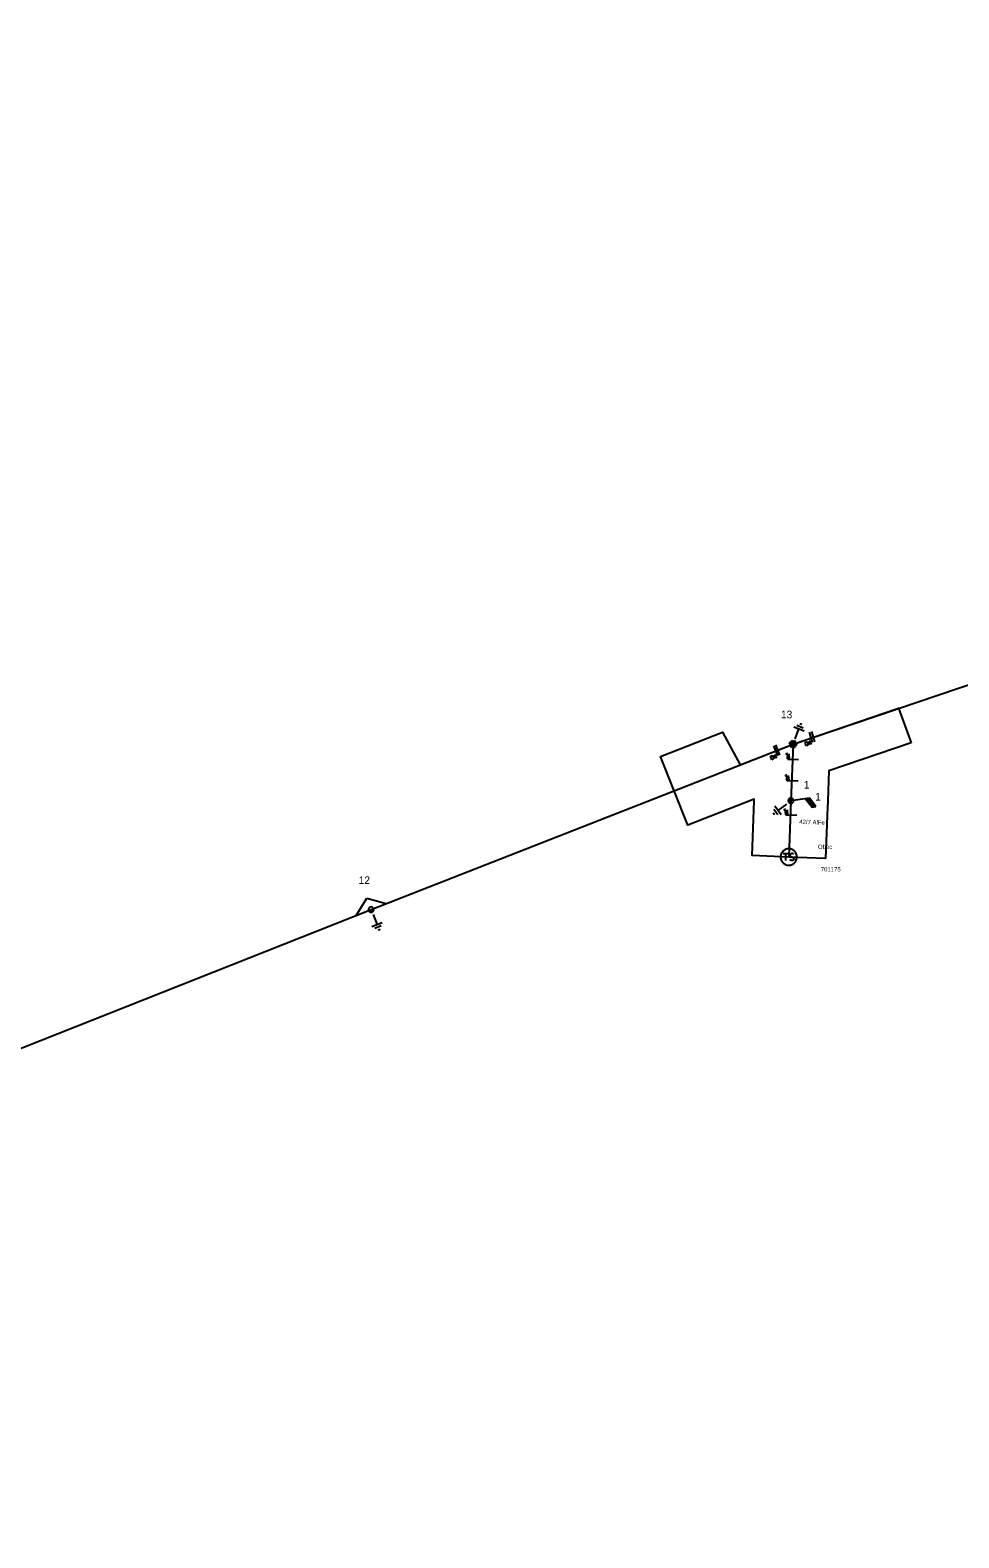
# Model space of a CAD drawing. Extents: x -788491 to -785797, y -1154753 to -1152002.
# Drawn here: x -786692.2 to -786477.8, y -1153491.5 to -1153143.3 of the extents above; entities that cross this region are included whole.
import ezdxf

# ---------------------------------------------------------------- set-up
doc = ezdxf.new("R2010")
doc.units = 0
for name, color, linetype in [('Default', 7, 'Continuous'), ('Vrstva 1', 7, 'Continuous'), ('Vrstva 11', 7, 'Continuous'), ('Vrstva 12', 7, 'Continuous'), ('Vrstva 13', 7, 'Continuous'), ('Vrstva 14', 7, 'Continuous'), ('Vrstva 15', 7, 'Continuous'), ('Vrstva 18', 7, 'Continuous'), ('Vrstva 2', 7, 'Continuous'), ('Vrstva 25', 7, 'Continuous'), ('Vrstva 26', 7, 'Continuous'), ('Vrstva 27', 7, 'Continuous'), ('Vrstva 35', 7, 'Continuous'), ('Vrstva 4', 7, 'Continuous'), ('Vrstva 57', 7, 'Continuous'), ('Vrstva 6', 7, 'Continuous')]:
    doc.layers.add(name, color=color, linetype=linetype)

# ---------------------------------------------------------------- blocks, each defined once
blk = doc.blocks.new('VN850')
at = {"layer": 'Vrstva 15'}
for points in [[(-0.56, 1.43), (-0.56, -1.07)], [(-0.01, 1.43), (-0.01, -1.07)], [(-2.09, -0.54), (-1.78, -0.54)], [(-2.09, -1.41), (-2.09, -0.54)], [(-1.78, -1.41), (-2.09, -1.41)], [(-1.78, -0.54), (-1.66, -0.6)], [(-1.67, -1.35), (-1.78, -1.41)], [(-1.59, -1.2), (-1.67, -1.35)], [(-1.66, -0.6), (-1.59, -0.75)], [(-1.59, -0.75), (-1.55, -0.96)], [(-1.55, -0.96), (-1.59, -1.2)], [(-1.26, -0.54), (-1.26, -1.41)], [(-0.85, -0.54), (-1.26, -1.09)], [(-1.13, -0.92), (-0.77, -1.41)]]:
    blk.add_lwpolyline(points, dxfattribs=at)
blk = doc.blocks.new('VN840')
at = {"layer": 'Vrstva 15'}
for points in [[(-0.01, 1.41), (-0.01, -1.09)], [(-1.51, -1.24), (-1.51, -1.15)], [(-1.48, -1.35), (-1.51, -1.24)], [(-1.33, -1.42), (-1.48, -1.35)], [(-1.27, -1.42), (-1.33, -1.42)], [(-1.13, -1.35), (-1.27, -1.42)], [(-1.09, -1.24), (-1.13, -1.35)], [(-1.09, -0.59), (-1.09, -1.24)], [(-0.68, -0.59), (-0.68, -1.42)], [(-0.68, -1.11), (-0.27, -0.59)], [(-0.54, -0.94), (-0.2, -1.42)]]:
    blk.add_lwpolyline(points, dxfattribs=at)
blk = doc.blocks.new('VN860')
at = {"layer": 'Vrstva 15'}
for points in [[(-3.74, 0), (0.01, 2.82)], [(0.01, 2.82), (3.76, 0)]]:
    blk.add_lwpolyline(points, dxfattribs=at)
blk = doc.blocks.new('VN440')
at = {"layer": 'Vrstva 2'}
for points in [[(1.22, 0), (1.21, 0.13), (1.19, 0.25), (1.16, 0.38), (1.11, 0.5), (1.05, 0.61), (0.98, 0.72), (0.9, 0.82), (0.81, 0.91), (0.71, 0.99), (0.6, 1.06), (0.49, 1.12), (0.37, 1.16), (0.25, 1.2), (0.12, 1.22), (-0.01, 1.22), (-0.14, 1.22), (-0.26, 1.2), (-0.39, 1.16), (-0.51, 1.12), (-0.62, 1.06), (-0.73, 0.99), (-0.83, 0.91), (-0.92, 0.82), (-1, 0.72), (-1.07, 0.61), (-1.13, 0.5), (-1.18, 0.38), (-1.21, 0.25), (-1.23, 0.13), (-1.24, 0), (-1.23, -0.13), (-1.21, -0.26), (-1.18, -0.38), (-1.13, -0.5), (-1.07, -0.62), (-1, -0.73), (-0.92, -0.83), (-0.83, -0.92), (-0.73, -1), (-0.62, -1.07), (-0.51, -1.13), (-0.39, -1.17), (-0.26, -1.2), (-0.14, -1.23), (-0.01, -1.23), (0.12, -1.23), (0.25, -1.2), (0.37, -1.17), (0.49, -1.13), (0.6, -1.07), (0.71, -1), (0.81, -0.92), (0.9, -0.83), (0.98, -0.73), (1.05, -0.62), (1.11, -0.5), (1.16, -0.38), (1.19, -0.26), (1.21, -0.13), (1.22, 0)], [(-1.24, 0), (1.22, 0)], [(-1.18, -0.34), (1.1, -0.34)], [(-1.01, -0.63), (0.97, -0.63)], [(-0.74, -0.92), (0.68, -0.92)]]:
    blk.add_lwpolyline(points, dxfattribs=at)
blk = doc.blocks.new('VN810')
at = {"layer": 'Vrstva 14'}
for points in [[(0, -1.25), (0, -3.75)], [(1.25, -3.75), (-1.25, -3.75)], [(0.77, -4.37), (-0.8, -4.37)], [(0, -5), (-0.25, -5)], [(0.27, -5), (0, -5)]]:
    blk.add_lwpolyline(points, dxfattribs=at)
blk = doc.blocks.new('VN610')
at = {"layer": 'Vrstva 6'}
for points in [[(1.88, 0), (1.87, 0.2), (1.84, 0.39), (1.79, 0.58), (1.72, 0.77), (1.63, 0.94), (1.52, 1.11), (1.4, 1.26), (1.26, 1.4), (1.1, 1.53), (0.94, 1.63), (0.76, 1.72), (0.58, 1.8), (0.39, 1.85), (0.19, 1.88), (-0.01, 1.89), (-0.21, 1.88), (-0.4, 1.85), (-0.59, 1.8), (-0.78, 1.72), (-0.95, 1.63), (-1.12, 1.53), (-1.27, 1.4), (-1.41, 1.26), (-1.54, 1.11), (-1.64, 0.94), (-1.73, 0.77), (-1.8, 0.58), (-1.86, 0.39), (-1.89, 0.2), (-1.9, 0), (-1.89, -0.2), (-1.86, -0.39), (-1.8, -0.58), (-1.73, -0.77), (-1.64, -0.95), (-1.54, -1.11), (-1.41, -1.27), (-1.27, -1.41), (-1.12, -1.53), (-0.95, -1.64), (-0.78, -1.73), (-0.59, -1.8), (-0.4, -1.85), (-0.21, -1.88), (-0.01, -1.89), (0.19, -1.88), (0.39, -1.85), (0.58, -1.8), (0.76, -1.73), (0.94, -1.64), (1.1, -1.53), (1.26, -1.41), (1.4, -1.27), (1.52, -1.11), (1.63, -0.95), (1.72, -0.77), (1.79, -0.58), (1.84, -0.39), (1.87, -0.2), (1.88, 0)], [(-1.27, 0.78), (-0.26, 0.78)], [(-0.76, 0.78), (-0.76, -0.79)], [(1.19, 0.66), (0.94, 0.78), (0.62, 0.78), (0.37, 0.66), (0.24, 0.47), (0.24, 0.4), (0.37, 0.22), (1.12, -0.16), (1.25, -0.32), (1.25, -0.48), (1.12, -0.67), (0.87, -0.79), (0.62, -0.79), (0.49, -0.73), (0.24, -0.6)]]:
    blk.add_lwpolyline(points, dxfattribs=at)
blk = doc.blocks.new('VN001')
at = {"layer": 'Default'}
for p, q in [((2.02, 3.53), (4.43, 3.53)), ((2.05, 3.58), (4.46, 3.58)), ((2.07, 3.63), (4.49, 3.63)), ((2.1, 3.68), (4.52, 3.68)), ((2.13, 3.73), (2.54, 3.73)), ((1.73, 3.03), (4.14, 3.03)), ((1.76, 3.08), (4.17, 3.08)), ((1.79, 3.13), (4.2, 3.13)), ((1.82, 3.18), (4.23, 3.18)), ((1.85, 3.23), (4.26, 3.23)), ((1.87, 3.28), (4.29, 3.28)), ((1.9, 3.33), (4.32, 3.33)), ((1.93, 3.38), (4.35, 3.38)), ((1.96, 3.43), (4.37, 3.43)), ((1.99, 3.48), (4.4, 3.48))]:
    blk.add_line(p, q, dxfattribs=at)
blk.add_lwpolyline([(2.13, 3.73), (0, 0)], dxfattribs=at)
blk.add_lwpolyline([(4.55, 3.73), (2.13, 3.73), (1.7, 2.98), (4.12, 2.99)], close=True, dxfattribs=at)
blk = doc.blocks.new('VN470')
at = {"layer": 'Vrstva 2'}
for points in [[(-1.23, 1.22), (1.23, 1.22)], [(-1.23, -1.23), (-1.23, 1.22)], [(-0.92, 0.9), (0.92, 0.9)], [(-0.92, -0.95), (-0.92, 0.9)], [(-0.61, 0.61), (0.61, 0.61)], [(-0.61, -0.62), (-0.61, 0.61)], [(-0.31, -0.27), (-0.31, 0.34)], [(-0.31, 0.34), (0.31, 0.34)], [(0, 1.22), (0, 1.97)], [(0.31, 0.34), (0.31, -0.27)], [(0.61, 0.61), (0.61, -0.62)], [(0.92, 0.9), (0.92, -0.95)], [(1.23, 1.22), (1.23, -1.23)], [(1.23, -1.23), (-1.23, -1.23)], [(0.92, -0.95), (-0.92, -0.95)], [(0.61, -0.62), (-0.61, -0.62)], [(0.31, -0.27), (-0.31, -0.27)], [(0, -1.23), (0, -1.98)]]:
    blk.add_lwpolyline(points, dxfattribs=at)

msp = doc.modelspace()

# ---------------------------------------------------------------- linework, layer by layer
at = {"layer": 'Vrstva 1'}
for points in [[(-786516.04, -1153308.16), (-786363.07, -1153256.35), (-786176.45, -1153193.34), (-786028.55, -1153143.31)], [(-787008.76, -1153502.68), (-786891.51, -1153456.67), (-786784.65, -1153414.25), (-786693.88, -1153378.27), (-786613.46, -1153346.39), (-786516.04, -1153308.16)]]:
    msp.add_lwpolyline(points, dxfattribs=at)
at = {"layer": 'Vrstva 35'}
msp.add_lwpolyline([(-786488.8, -1153307.91), (-786507.76, -1153314.33), (-786508.03, -1153321.26), (-786508.04, -1153321.58), (-786508.12, -1153322.74), (-786508.53, -1153334.57), (-786517.02, -1153334.25), (-786525.51, -1153333.93), (-786525.03, -1153321.26), (-786525.02, -1153320.86), (-786540.36, -1153326.88), (-786543.51, -1153318.94), (-786546.64, -1153311.06), (-786532.33, -1153305.45), (-786528.28, -1153312.96), (-786516.04, -1153308.16), (-786491.67, -1153299.91)], close=True, dxfattribs=at)
at = {"layer": 'Vrstva 4'}
for points in [[(-786516.04, -1153308.16), (-786516.53, -1153321.26)], [(-786516.53, -1153321.26), (-786517.02, -1153334.25)]]:
    msp.add_lwpolyline(points, dxfattribs=at)

# ---------------------------------------------------------------- block references
at = {"layer": 'Vrstva 11', "rotation": -52.69868055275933}
msp.add_blockref('VN001', (-786516.53, -1153321.26), dxfattribs=at)
at = {"layer": 'Vrstva 13', "xscale": 0.5}
for name, p, yscale, rotation in [('VN470', (-786516.04, -1153308.16), 0.49999999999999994, 21.399183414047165), ('VN440', (-786516.53, -1153321.26), 0.5, -89.38492493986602), ('VN440', (-786613.46, -1153346.39), 0.49999999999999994, 21.399183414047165)]:
    msp.add_blockref(name, p, dxfattribs=dict(at, yscale=yscale, rotation=rotation))
at = {"layer": 'Vrstva 15'}
for p, rotation in [((-786516.04, -1153308.16), 158.61622792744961), ((-786516.53, -1153321.26), -52.69868049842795), ((-786613.46, -1153346.39), 21.399183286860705)]:
    msp.add_blockref('VN810', p, dxfattribs=dict(at, rotation=rotation))
at = {"layer": 'Vrstva 18'}
for name, p, rotation in [('VN850', (-786511.39, -1153306.62), 16.067366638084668), ('VN850', (-786519.53, -1153309.7), 21.399183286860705), ('VN840', (-786516.16, -1153311.78), -90.13578053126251), ('VN840', (-786516.28, -1153316.73), -88.60159993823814), ('VN840', (-786516.54, -1153324.62), -87.7731360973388), ('VN860', (-786613.46, -1153346.39), 21.399183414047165)]:
    msp.add_blockref(name, p, dxfattribs=dict(at, rotation=rotation))
at = {"layer": 'Vrstva 25'}
msp.add_blockref('VN610', (-786517.02, -1153334.25), dxfattribs=at)

# ---------------------------------------------------------------- texts
at = {"layer": 'Vrstva 12'}
msp.add_text('1', height=1.75, dxfattribs=at).set_placement((-786510.92, -1153321.21))
at = {"layer": 'Vrstva 14'}
for s, p in [('13', (-786518.82, -1153302.22)), ('1', (-786513.57, -1153318.44)), ('12', (-786616.33, -1153340.48))]:
    msp.add_text(s, height=1.75, dxfattribs=at).set_placement(p)
at = {"layer": 'Vrstva 26'}
msp.add_text('701175', height=1, dxfattribs=at).set_placement((-786509.63, -1153337.58))
at = {"layer": 'Vrstva 27'}
msp.add_text('Obec', height=1, dxfattribs=at).set_placement((-786510.28, -1153332.39))
at = {"layer": 'Vrstva 57'}
msp.add_text('42/7 AlFe', height=1, rotation=357.942, dxfattribs=at).set_placement((-786514.62, -1153326.6))

doc.saveas('drawing.dxf')
